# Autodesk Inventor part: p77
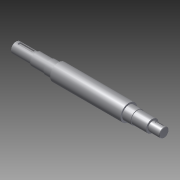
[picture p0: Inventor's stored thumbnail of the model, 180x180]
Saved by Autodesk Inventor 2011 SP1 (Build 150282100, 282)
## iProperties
Created: 2014-02
Part Number: p77
Document SubType Name: Modeling
Designer: Administrator
Density: 1 g/cm^3
Author: Administrator
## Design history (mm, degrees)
sketch "草图1" dims "d18" = 1
  geometry: L1 (0, 0)-(0, -14); L2 (0, -14)-(55, -14); L3 (55, -14)-(55, -16.5); L4 (55, -16.5)-(92, -16.5); L5 (92, -16.5)-(92, -18); L6 (92, -18)-(115, -18); L7 (115, -18)-(115, -22.5); L8 (115, -22.5)-(305, -22.5); L9 (305, -22.5)-(305, -18); L10 (305, -18)-(328, -18); L11 (328, -18)-(328, -16.5); L12 (328, -16.5)-(368, -16.5); L13 (368, -16.5)-(368, -11.5); L14 (368, -11.5)-(371, -11.5); L15 (371, -11.5)-(371, -12.5); L16 (371, -12.5)-(400, -12.5); L17 (400, -12.5)-(400, 0); L18 (400, 0)-(0, 0)
  constraints: 36 end point, 9 perpendicular, 7 parallel, 1 vertical
  dimensions: "d0" = 14 distance of L1.start L1.end; "d1" = 55 distance of L1.end L2.end; "d2" = 2.5 distance of L2.end L3.end; "d3" = 37 distance of L3.end L4.end; "d4" = 1.5 distance of L4.end L5.end; "d5" = 23 distance of L5.end L6.end; "d6" = 4.5 distance of L6.end L7.end; "d7" = 190 distance of L7.end L8.end; "d8" = 4.5 distance of L8.end L9.end; "d9" = 23 distance of L9.end L10.end; "d10" = 1.5 distance of L10.end L11.end; "d11" = 40 distance of L11.end L12.end; "d12" = 5 distance of L12.end L13.end; "d13" = 3 distance of L13.end L14.end; "d14" = 1 distance of L14.end L15.end; "d15" = 29 distance of L15.end L16.end; "d16" = 12.5 distance of L16.end L17.end
revolve "旋转1" sketch "草图1" stored, may be unused: angle "d17" = 90 deg
chamfer "倒角1" distance "d18" = 1; stored, may be unused: second distance "d19" = 2, angle "d20" = 45 deg
hole "Hole1" diameter "d23" = 4.917; stored, may be unused: countersink angle "d27" = 82 deg, drill point angle "d29" = 118 deg; dims "d21" = 10, "d22" = 10, "d24" = 20, "d25" = 3.023, "d26" = 2, "d28" = 25
sketch "草图2" dims "d30" = 20
  geometry: C1 r 13 at (0, 0) reference; 2 further points
  constraints: 1 coincident, 1 horizontal alignment, 2 other
hole "Hole2" sketch "草图2" at (-10, 0) diameter "d31" = 3; stored, may be unused: countersink angle "d35" = 82 deg, drill point angle "d37" = 118 deg; dims "d32" = 20, "d33" = 3.023, "d34" = 2, "d36" = 6
sketch "草图3"
  geometry: L1 (-55, 14)-(-1, 14) reference; L2 (-8, 14)-(-48, 14); L3 (-48, 14)-(-48, 10); L4 (-48, 10)-(-8, 10); L5 (-8, 10)-(-8, 14); L6 (0, 13)-(0, -13) reference; L7 (-55, -14)-(-55, 14) reference; 1 further point
  constraints: 8 end point, 2 parallel, 1 horizontal, 1 perpendicular, 1 point on line
  dimensions: "d38" = 40 distance of L3.end L4.end; "d39" = 4 distance of L2.end L3.end; "d40" = 7 distance between parallel lines of L7 L3
extrude "拉伸1" cut sketch "草图3" stored distance "d41" = 8; taper "d42" = 0 deg
sketch "草图4"
  geometry: L1 (-371, -12.5)-(-371, 12.5) reference; L2 (-400, -12.5)-(-400, 12.5) reference; L3 (-400, 12.5)-(-371, 12.5) reference; L4 (-374, 12.5)-(-394, 12.5); L5 (-394, 12.5)-(-394, 9); L6 (-394, 9)-(-374, 9); L7 (-374, 9)-(-374, 12.5); 1 further point
  constraints: 8 end point, 2 parallel, 1 horizontal, 1 perpendicular, 1 point on line
  dimensions: "d43" = 20 distance of L5.end L6.end; "d44" = 3.5 distance of L4.end L5.end; "d45" = 6 distance between parallel lines of L2 L5
extrude "拉伸2" cut sketch "草图4" distance "d46" = 6; taper "d47" = 0 deg
mirror "镜像1"
chamfer "倒角2" distance "d48" = 1; stored, may be unused: second distance "d49" = 2, angle "d50" = 45 deg
fillet "圆角1" dims "d51" = 0.5
chamfer "倒角3" distance "d52" = 0.5; stored, may be unused: second distance "d53" = 2, angle "d54" = 45 deg
chamfer "倒角4" distance "d55" = 0.5; stored, may be unused: second distance "d56" = 2, angle "d57" = 45 deg
node "实体1"
node "投影回路1"
